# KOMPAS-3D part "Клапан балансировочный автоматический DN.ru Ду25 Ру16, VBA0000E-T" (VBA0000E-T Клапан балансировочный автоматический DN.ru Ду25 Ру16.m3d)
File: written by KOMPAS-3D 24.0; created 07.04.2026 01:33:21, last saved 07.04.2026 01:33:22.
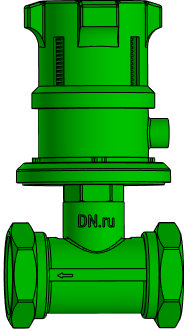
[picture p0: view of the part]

Document properties: Автор: tyuri; Полное имя файла: D:\Аутсорс\VBA0000E-T Клапан балансировочный автоматический DN.ru\DN25\VBA0000E-T Клапан балансировочный автоматический DN.ru Ду25 Ру16.m3d

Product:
- Body: Тело 6  | qty 1
    Масса: 1.195907
- Part/product: Клапан балансировочный автоматический DN.ru Ду25 Ру16  | designation VBA0000E-T
    Масса: 0.788
    Раздел спецификации: Прочие изделия
    Примечание: D080-01202

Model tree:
1. Операция без истории:1

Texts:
  Точка начала. Х
  Точка начала. Y
  Точка начала. Z
  VBA0000E-T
